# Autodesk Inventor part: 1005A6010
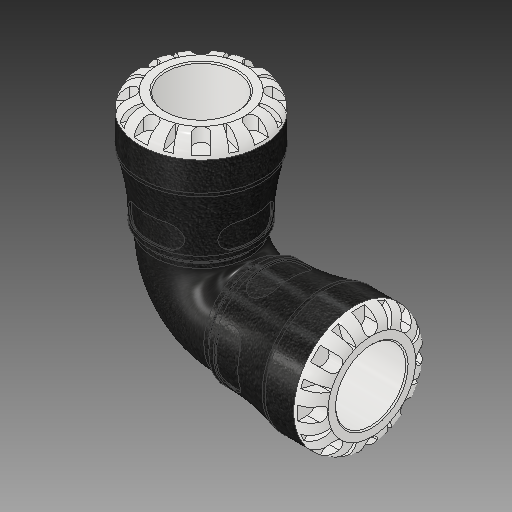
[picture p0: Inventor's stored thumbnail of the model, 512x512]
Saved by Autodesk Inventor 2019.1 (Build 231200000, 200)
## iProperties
Created: 2016-12
Part Number: 1005A6010
Material: PVC-Piping
Description: PLASSON 90° ELBOW 1''IPS SERIES 1
Document SubType Name: Modeling
Designer: KIM
Mass: 664.223 g
Surface Area: 733.008 cm^2
Volume: 474.445 cm^3
Density: 1.4 g/cm^3
Appearance: Black Cast
Author: KIM
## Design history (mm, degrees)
derived "1005A.ipt"
feature "Solid1::1005A.ipt"
tag "TaggingFeature1"
body "Solid1"
other parameters: "d1" = 22.61616, "d2" = 33.3, "d3" = 41.625, "d4" = 57.912, "d8" = 49.2252, "d13" = 6.5148, "d14" = 6.5148, "d15" = 0, "d17" = 360 deg, "d19" = 8 deg, "d20" = 0.666, "d21" = 0.666, "d22" = 8 deg, "d24" = 0, "d26" = 360 deg, "d33" = 5.7912, "d43" = 45.17136, "d51" = 0.57912, "d54" = 11.655, "d55" = 7.326, "d57" = 12.76901, "d58" = 0, "d74" = 0, "d77" = 2.775, "d78" = 53.848, "d82" = 0.666, "d115" = 360 deg, "d207" = 90 deg, "d228" = 9.90675, "d247" = 1.15824, "d248" = 3.23088, "d268" = 27.07386, "d269" = 3.23088, "d270" = 81.026, "d272" = 90 deg, "d274" = 0, "d275" = 0, "d_" = 33.3, "E_" = 57.912, "l_" = 53.848, "A_" = 81.026, "d9" = 8.1435, "d11" = 57.912, "d12" = 41.625
